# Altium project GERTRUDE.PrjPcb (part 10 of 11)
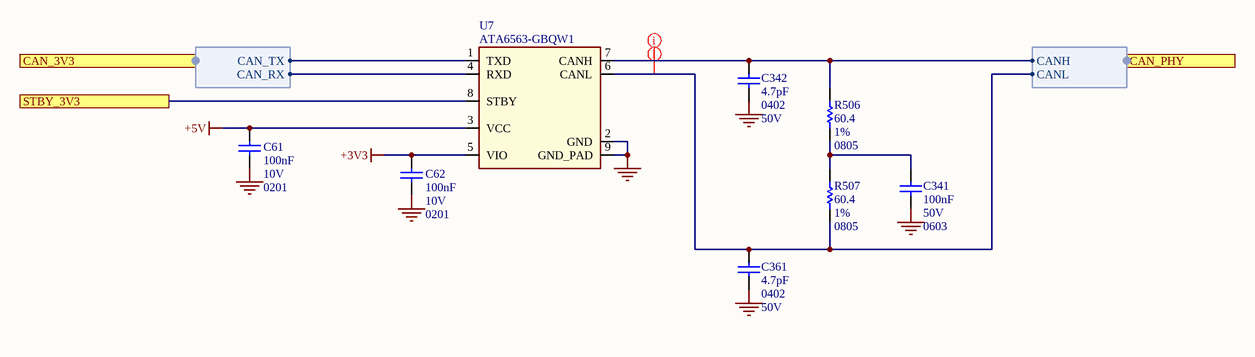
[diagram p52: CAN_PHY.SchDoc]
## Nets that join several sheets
7V-24V: USB_PD_CONTROLLER (D9.A), HEADERS_UNO (F2.1), POWER (11 pins), HEADERS_JOMEGA (8 pins), HEADERS_JMEDIA_JMISC (F3.1)
+1.28V: POWER_REGULATORS_CARRIER (5 pins), AUDIO_CODEC (C136.2 C146.2 U23.36)
+1V1: ETH_PHY (12 pins), POWER_REGULATORS_CARRIER (8 pins), PCIE_PACKET_SWITCH (11 pins), PCIE_USB (39 pins)
+1V8: U_ETH/U_ETH_PHY/U_LOAD_SWITCH_5V (U27_3.6 U27_3.11), POWER (R21.2 R22.2 R265.1 TP84.X), AUDIO_CODEC (7 pins), HDMI_CONVERTER (5 pins), STM32 (R218.1)
+3V3: TOP (11 pins), MODULE_PWR (27 pins), MODULE_CONTROL (12 pins), USB_MUX (R475.2), USB_PD_CONTROLLER (R275.1), U_USB/U_LOAD_SWITCH_5V (C179_1.2 U27_1.3), U_USB/U_LOAD_SWITCH_5V (C179_2.2 U27_2.3), U_ETH/U_ETH_PHY/U_LOAD_SWITCH_5V (C179_3.2 U27_3.3), ETH_RJ45 (J2.14 J2.16), POWER (9 pins), POWER_DCDC_SOM (23 pins), POWER_REGULATORS_CARRIER (9 pins), U_POWER/U_LOAD_SWITCH_5V (C179_4.2 U27_4.3), U_POWER/U_LOAD_SWITCH_5V (C179_5.2 U27_5.3 U27_5.6 U27_5.11), HDMI_CONVERTER (L16.1), U_MIPI/U_MIPI_MUX (C69_1.2 U10_1.1), U_MIPI/U_MIPI_MUX (C69_2.2 U10_2.1), U_MIPI/U_MIPI_FLAT_22PIN (D15_1.2 J3_1.22), U_MIPI/U_MIPI_FLAT_22PIN (D15_2.2 J3_2.22), U_MIPI/U_MIPI_MUX (C69_3.2 U10_3.1), U_MIPI/U_MIPI_FLAT_22PIN (D15_3.2 J3_3.22), U_MIPI/U_TRANSLATOR_4CH (C175_2.2 U21_2.11), HEADERS_JOMEGA (JOMEGA.91 JOMEGA.93 JOMEGA.95), STM32 (35 pins), U_MICROCONTROLLER/U_LED/U_LED_RGB (DL1_1.1), U_MICROCONTROLLER/U_LED/U_LED_RGB (DL1_2.1), U_MICROCONTROLLER/U_LED/U_LED_RGB (DL1_3.1), U_MICROCONTROLLER/U_LED/U_LED_RGB (DL1_4.1), ANALOG_SWITCH (C274.2 U28.4 U28.5), U_MICROCONTROLLER/U_TRANSLATOR_4CH (C175_3.2 U21_3.11), HEADERS_JMEDIA_JMISC (5 pins), HEADERS_JCTL (R317.2), T8CH_ (C174_5.2 U33_5.19), HEATSINK_FAN (C306.2 R261.2 R455.2 U32.5), PCIE (R327.1 R328.1 R329.1), PCIE_PACKET_SWITCH (37 pins), U_PCIE/U_PCIE_NVME/U_LOAD_SWITCH_5V (C179_6.2 U27_6.3 U27_6.6 U27_6.11), WIFI_BLE (12 pins), U_PCIE/U_WIFI_BLE/U_TRANSLATOR_4CH (C175_4.2 U21_4.11), PCIE_USB (13 pins), U_PCIE/U_TRANSLATOR_4CH (C175_5.2 U21_5.11), CAN_PHY (C62.2 U7.5)
+3V3_LIMITED: HEADERS_UNO (JANALOG.2 JANALOG.4), POWER (C222.2), U_POWER/U_LOAD_SWITCH_5V (U27_5.7 U27_5.8 U27_5.9 U27_5.10), HEADERS_JHAT (6 pins), U_HEADERS_JHAT/T8CH_ (C174_2.2 U33_2.19), U_HEADERS_JHAT/T8CH_ (C174_3.2 U33_3.19), U_HEADERS_JHAT/T8CH_ (C174_4.2 U33_4.19), U_HEADERS_JHAT/U_TRANSLATOR_4CH (C175_1.2 U21_1.11), QWIIC (C271.2 D82.2 J13.2)
+5V: USB_PD_CONTROLLER (R276.2), U_USB/U_LOAD_SWITCH_5V (U27_1.6 U27_1.11), U_USB/U_LOAD_SWITCH_5V (U27_2.6 U27_2.11), POWER (R336.1), POWER_REGULATORS_CARRIER (12 pins), U_POWER/U_LOAD_SWITCH_5V (U27_4.6 U27_4.11), AUDIO_CODEC (C165.2 C166.2 U23.14 U23.15), HDMI_CONNECTOR (D3.A R492.2 R495.2), HEADERS_JOMEGA (JOMEGA.97 JOMEGA.99), HEADERS_JMEDIA_JMISC (JMISC.54 JMISC.56), HEATSINK_FAN (5 pins), CAN_PHY (C61.2 U7.3)
+5V_LIMITED: HEADERS_UNO (JANALOG.5 JSPI.2), POWER (C221.2), U_POWER/U_LOAD_SWITCH_5V (U27_4.7 U27_4.8 U27_4.9 U27_4.10), HEADERS_JHAT (J6.2 J6.4)
CYPD_VDDIO: USB_MUX (R476.2), USB_PD_CONTROLLER (13 pins), U_USB/U_USB_PD_CONTROLLER/T8CH_ (C174_1.2 U33_1.19)
GND: TOP (12 pins), MODULE_GND (1526 pins), MODULE_PWR (12 pins), MODULE_SAIL (TP30.X), MODULE_SAIL_FLASH (7 pins), MODULE_STRAPS_MD (10 pins), MODULE_STRAPS_SAIL (13 pins), MODULE_CONTROL (12 pins), USB (12 pins), USB_USBC (19 pins), USB_MUX (13 pins), USB_PD_CONTROLLER (43 pins), U_USB/U_USB_PD_CONTROLLER/T8CH_ (5 pins), USB_USBA (16 pins), U_USB/U_LOAD_SWITCH_5V (C179_1.1 C246_1.1 U27_1.2), U_USB/U_LOAD_SWITCH_5V (C179_2.1 C246_2.1 U27_2.2), ETH (C67.1 C68.1 U8.3 U9.3), ETH_PHY (45 pins), U_ETH/U_ETH_PHY/U_LOAD_SWITCH_5V (C179_3.1 C246_3.1 U27_3.2), ETH_RJ45 (C66.2 R109.1), HEADERS_UNO (5 pins), POWER (30 pins), POWER_DCDC_SOM (51 pins), POWER_REGULATORS_CARRIER (49 pins), U_POWER/U_LOAD_SWITCH_5V (C179_4.1 C246_4.1 U27_4.2), U_POWER/U_LOAD_SWITCH_5V (C179_5.1 C246_5.1 U27_5.2), AUDIO_CODEC (24 pins), HEADERS_JHAT (8 pins), U_HEADERS_JHAT/T8CH_ (5 pins), U_HEADERS_JHAT/T8CH_ (5 pins), U_HEADERS_JHAT/T8CH_ (5 pins), U_HEADERS_JHAT/U_TRANSLATOR_4CH (C172_1.1 C175_1.1 C220_1.2 U21_1.6), VIDEO (5 pins), HDMI (R269.1), HDMI_CONNECTOR (18 pins), HDMI_CONVERTER (22 pins), U_MIPI/U_MIPI_MUX (8 pins), U_MIPI/U_MIPI_MUX (8 pins), U_MIPI/U_MIPI_FLAT_22PIN (17 pins), U_MIPI/U_MIPI_FLAT_22PIN (17 pins), U_MIPI/U_MIPI_MUX (8 pins), U_MIPI/U_MIPI_FLAT_22PIN (17 pins), U_MIPI/U_TRANSLATOR_4CH (C172_2.1 C175_2.1 C220_2.2 U21_2.6), PUSHBUTTONS (6 pins), HEADERS_JOMEGA (50 pins), MICROCONTROLLER (R184.1), STM32 (59 pins), QWIIC (6 pins), ANALOG_SWITCH (C274.1 U28.2), U_MICROCONTROLLER/U_TRANSLATOR_4CH (C172_3.1 C175_3.1 C220_3.2 U21_3.6), HEADERS_JMEDIA_JMISC (63 pins), HEADERS_JCTL (12 pins), T8CH_ (5 pins), HEATSINK_FAN (13 pins), PCIE (R315.1 R323.1 R468.1), PCIE_PACKET_SWITCH (42 pins), PCIE_NVME (40 pins), U_PCIE/U_PCIE_NVME/U_LOAD_SWITCH_5V (C179_6.1 C246_6.1 U27_6.2), WIFI_BLE (63 pins), U_PCIE/U_WIFI_BLE/U_TRANSLATOR_4CH (C172_4.1 C175_4.1 C220_4.2 U21_4.6), PCIE_USB (43 pins), U_PCIE/U_TRANSLATOR_4CH (C172_5.1 C175_5.1 C220_5.2 U21_5.6), CAN_PHY (7 pins)
SOM_VCOIN: MODULE_PWR (R399.1), HEADERS_JMEDIA_JMISC (R508.2)
SOM_VREG_MDPX3_1P8: TOP (10 pins), MODULE_PWR (MODULE1.BD42 MODULE1.BE42 MODULE1.BF42 TP88.X), MODULE_STRAPS_MD (10 pins), USB_PD_CONTROLLER (R330.1 R331.1 R332.1), U_USB/U_USB_PD_CONTROLLER/T8CH_ (C173_1.2 R168_1.2 U33_1.2), POWER (R21.1 R497.2), POWER_REGULATORS_CARRIER (R146.1 R147.1 U16.5 U17.5), AUDIO_CODEC (R270.2), HEADERS_JHAT (R422.1 R423.1 R424.1 R425.1), U_HEADERS_JHAT/T8CH_ (C173_2.2 R168_2.2 U33_2.2), U_HEADERS_JHAT/T8CH_ (C173_3.2 R168_3.2 U33_3.2), U_HEADERS_JHAT/T8CH_ (C173_4.2 R168_4.2 U33_4.2), U_HEADERS_JHAT/U_TRANSLATOR_4CH (C172_1.2 R326_1.2 U21_1.1), VIDEO (8 pins), U_MIPI/U_TRANSLATOR_4CH (C172_2.2 R326_2.2 U21_2.1), HEADERS_JOMEGA (JOMEGA.79 JOMEGA.81), MICROCONTROLLER (R412.1), STM32 (R351.1), U_MICROCONTROLLER/U_TRANSLATOR_4CH (C172_3.2 R326_3.2 U21_3.1), HEADERS_JMEDIA_JMISC (JMISC.57), HEADERS_JCTL (D63.2 JCTL.9 R166.1), T8CH_ (C173_5.2 R168_5.2 U33_5.2), PCIE (R319.1 R320.1 R321.1 R322.2), PCIE_NVME (R224.1 R414.2 R415.2 R416.2), WIFI_BLE (R23.2 R314.1 R465.2), U_PCIE/U_WIFI_BLE/U_TRANSLATOR_4CH (C172_4.2 R326_4.2 U21_4.1), U_PCIE/U_TRANSLATOR_4CH (C172_5.2 R326_5.2 U21_5.1)
SOM_VREG_S5S_SPX3_1P8: MODULE_PWR (MODULE1.AW45 MODULE1.AW46), MODULE_SAIL (TP1.X), MODULE_SAIL_FLASH (12 pins), MODULE_STRAPS_SAIL (13 pins), HEADERS_JOMEGA (JOMEGA.77), HEADERS_JCTL (R458.1)
VBAT: STM32 (C63.2 C282.2 U3.D3), HEADERS_JMEDIA_JMISC (R509.2)
1V05_PG (PULLUP 1V8): ETH_PHY (R85.1), POWER (R265.2), POWER_REGULATORS_CARRIER (U17.1)
3V3_PG (PULLUP 3V3): TOP (R349.1), POWER_DCDC_SOM (R124.2 U11.1 U11.2)
A_CLK_N: U_MIPI/U_MIPI_MUX (U10_1.18), HEADERS_JMEDIA_JMISC (D91.1 D91.10 JMEDIA.3)
A_CLK_N: U_MIPI/U_MIPI_MUX (U10_2.18), HEADERS_JMEDIA_JMISC (D93.4 D93.7 JMEDIA.33)
A_CLK_N: U_MIPI/U_MIPI_MUX (U10_3.18), HEADERS_JMEDIA_JMISC (D96.2 D96.9 JMEDIA.42)
A_CLK_P: U_MIPI/U_MIPI_MUX (U10_1.19), HEADERS_JMEDIA_JMISC (D91.2 D91.9 JMEDIA.5)
A_CLK_P: U_MIPI/U_MIPI_MUX (U10_2.19), HEADERS_JMEDIA_JMISC (D93.5 D93.6 JMEDIA.35)
A_CLK_P: U_MIPI/U_MIPI_MUX (U10_3.19), HEADERS_JMEDIA_JMISC (D96.1 D96.10 JMEDIA.40)
A_LN0_N: U_MIPI/U_MIPI_MUX (U10_1.37), HEADERS_JMEDIA_JMISC (D90.1 D90.10 JMEDIA.12)
A_LN0_N: U_MIPI/U_MIPI_MUX (U10_2.37), HEADERS_JMEDIA_JMISC (D92.4 D92.7 JMEDIA.21)
A_LN0_N: U_MIPI/U_MIPI_MUX (U10_3.37), HEADERS_JMEDIA_JMISC (D97.2 D97.9 JMEDIA.54)
A_LN0_P: U_MIPI/U_MIPI_MUX (U10_1.38), HEADERS_JMEDIA_JMISC (D90.2 D90.9 JMEDIA.10)
A_LN0_P: U_MIPI/U_MIPI_MUX (U10_2.38), HEADERS_JMEDIA_JMISC (D92.5 D92.6 JMEDIA.23)
A_LN0_P: U_MIPI/U_MIPI_MUX (U10_3.38), HEADERS_JMEDIA_JMISC (D97.1 D97.10 JMEDIA.52)
A_LN1_N: U_MIPI/U_MIPI_MUX (U10_1.35), HEADERS_JMEDIA_JMISC (D90.4 D90.7 JMEDIA.6)
A_LN1_N: U_MIPI/U_MIPI_MUX (U10_2.35), HEADERS_JMEDIA_JMISC (D93.1 D93.10 JMEDIA.27)
A_LN1_N: U_MIPI/U_MIPI_MUX (U10_3.35), HEADERS_JMEDIA_JMISC (D96.5 D96.6 JMEDIA.48)
A_LN1_P: U_MIPI/U_MIPI_MUX (U10_1.36), HEADERS_JMEDIA_JMISC (D90.5 D90.6 JMEDIA.4)
A_LN1_P: U_MIPI/U_MIPI_MUX (U10_2.36), HEADERS_JMEDIA_JMISC (D93.2 D93.9 JMEDIA.29)
A_LN1_P: U_MIPI/U_MIPI_MUX (U10_3.36), HEADERS_JMEDIA_JMISC (D96.4 D96.7 JMEDIA.46)
A_LN2_N: U_MIPI/U_MIPI_MUX (U10_1.33), HEADERS_JMEDIA_JMISC (D91.4 D91.7 JMEDIA.9)
A_LN2_N: U_MIPI/U_MIPI_MUX (U10_2.33), HEADERS_JMEDIA_JMISC (D94.1 D94.10 JMEDIA.39)
A_LN2_N: U_MIPI/U_MIPI_MUX (U10_3.33), HEADERS_JMEDIA_JMISC (D95.5 D95.6 JMEDIA.36)
A_LN2_P: U_MIPI/U_MIPI_MUX (U10_1.34), HEADERS_JMEDIA_JMISC (D91.5 D91.6 JMEDIA.11)
A_LN2_P: U_MIPI/U_MIPI_MUX (U10_2.34), HEADERS_JMEDIA_JMISC (D94.2 D94.9 JMEDIA.41)
A_LN2_P: U_MIPI/U_MIPI_MUX (U10_3.34), HEADERS_JMEDIA_JMISC (D95.4 D95.7 JMEDIA.34)
A_LN3_N: U_MIPI/U_MIPI_MUX (U10_1.31), HEADERS_JMEDIA_JMISC (D92.1 D92.10 JMEDIA.15)
A_LN3_N: U_MIPI/U_MIPI_MUX (U10_2.31), HEADERS_JMEDIA_JMISC (D94.4 D94.7 JMEDIA.45)
A_LN3_N: U_MIPI/U_MIPI_MUX (U10_3.31), HEADERS_JMEDIA_JMISC (D95.2 D95.9 JMEDIA.30)
A_LN3_P: U_MIPI/U_MIPI_MUX (U10_1.32), HEADERS_JMEDIA_JMISC (D92.2 D92.9 JMEDIA.17)
A_LN3_P: U_MIPI/U_MIPI_MUX (U10_2.32), HEADERS_JMEDIA_JMISC (D94.5 D94.6 JMEDIA.47)
A_LN3_P: U_MIPI/U_MIPI_MUX (U10_3.32), HEADERS_JMEDIA_JMISC (D95.1 D95.10 JMEDIA.28)
B_CLK_N: HDMI_CONVERTER (U22.F2), U_MIPI/U_MIPI_MUX (U10_1.20)
B_CLK_N: U_MIPI/U_MIPI_MUX (U10_2.20), U_MIPI/U_MIPI_FLAT_22PIN (D7_2.1 D7_2.10 J3_2.8)
B_CLK_N: U_MIPI/U_MIPI_FLAT_22PIN (D7_1.1 D7_1.10 J3_1.8), U_MIPI/U_MIPI_MUX (U10_3.20)
B_CLK_P: HDMI_CONVERTER (U22.G2), U_MIPI/U_MIPI_MUX (U10_1.21)
B_CLK_P: U_MIPI/U_MIPI_MUX (U10_2.21), U_MIPI/U_MIPI_FLAT_22PIN (D7_2.2 D7_2.9 J3_2.9)
B_CLK_P: U_MIPI/U_MIPI_FLAT_22PIN (D7_1.2 D7_1.9 J3_1.9), U_MIPI/U_MIPI_MUX (U10_3.21)
B_LN0_N: HDMI_CONVERTER (U22.F3), U_MIPI/U_MIPI_MUX (U10_1.28)
B_LN0_N: U_MIPI/U_MIPI_MUX (U10_2.28), U_MIPI/U_MIPI_FLAT_22PIN (D6_2.1 D6_2.10 J3_2.2)
B_LN0_N: U_MIPI/U_MIPI_FLAT_22PIN (D6_1.1 D6_1.10 J3_1.2), U_MIPI/U_MIPI_MUX (U10_3.28)
B_LN0_P: HDMI_CONVERTER (U22.G3), U_MIPI/U_MIPI_MUX (U10_1.29)
B_LN0_P: U_MIPI/U_MIPI_MUX (U10_2.29), U_MIPI/U_MIPI_FLAT_22PIN (D6_2.2 D6_2.9 J3_2.3)
B_LN0_P: U_MIPI/U_MIPI_FLAT_22PIN (D6_1.2 D6_1.9 J3_1.3), U_MIPI/U_MIPI_MUX (U10_3.29)
B_LN1_N: HDMI_CONVERTER (U22.F4), U_MIPI/U_MIPI_MUX (U10_1.26)
B_LN1_N: U_MIPI/U_MIPI_MUX (U10_2.26), U_MIPI/U_MIPI_FLAT_22PIN (D6_2.4 D6_2.7 J3_2.5)
B_LN1_N: U_MIPI/U_MIPI_FLAT_22PIN (D6_1.4 D6_1.7 J3_1.5), U_MIPI/U_MIPI_MUX (U10_3.26)
B_LN1_P: HDMI_CONVERTER (U22.G4), U_MIPI/U_MIPI_MUX (U10_1.27)
B_LN1_P: U_MIPI/U_MIPI_MUX (U10_2.27), U_MIPI/U_MIPI_FLAT_22PIN (D6_2.5 D6_2.6 J3_2.6)
B_LN1_P: U_MIPI/U_MIPI_FLAT_22PIN (D6_1.5 D6_1.6 J3_1.6), U_MIPI/U_MIPI_MUX (U10_3.27)
B_LN2_N: HDMI_CONVERTER (U22.F5), U_MIPI/U_MIPI_MUX (U10_1.24)
B_LN2_N: U_MIPI/U_MIPI_MUX (U10_2.24), U_MIPI/U_MIPI_FLAT_22PIN (D7_2.4 D7_2.7 J3_2.11)
B_LN2_N: U_MIPI/U_MIPI_FLAT_22PIN (D7_1.4 D7_1.7 J3_1.11), U_MIPI/U_MIPI_MUX (U10_3.24)
B_LN2_P: HDMI_CONVERTER (U22.G5), U_MIPI/U_MIPI_MUX (U10_1.25)
B_LN2_P: U_MIPI/U_MIPI_MUX (U10_2.25), U_MIPI/U_MIPI_FLAT_22PIN (D7_2.5 D7_2.6 J3_2.12)
B_LN2_P: U_MIPI/U_MIPI_FLAT_22PIN (D7_1.5 D7_1.6 J3_1.12), U_MIPI/U_MIPI_MUX (U10_3.25)
B_LN3_N: HDMI_CONVERTER (U22.F6), U_MIPI/U_MIPI_MUX (U10_1.22)
B_LN3_N: U_MIPI/U_MIPI_MUX (U10_2.22), U_MIPI/U_MIPI_FLAT_22PIN (D8_2.1 D8_2.10 J3_2.14)
B_LN3_N: U_MIPI/U_MIPI_FLAT_22PIN (D8_1.1 D8_1.10 J3_1.14), U_MIPI/U_MIPI_MUX (U10_3.22)
B_LN3_P: HDMI_CONVERTER (U22.G6), U_MIPI/U_MIPI_MUX (U10_1.23)
B_LN3_P: U_MIPI/U_MIPI_MUX (U10_2.23), U_MIPI/U_MIPI_FLAT_22PIN (D8_2.2 D8_2.9 J3_2.15)
B_LN3_P: U_MIPI/U_MIPI_FLAT_22PIN (D8_1.2 D8_1.9 J3_1.15), U_MIPI/U_MIPI_MUX (U10_3.23)
BOOT0: HEADERS_UNO (JANALOG.1), MICROCONTROLLER (R151.1), STM32 (R352.2 R385.1 TP90.X)
CLKREQ_N_1V8: MODULE_MD (MODULE1.AW17), PCIE (R320.2), U_PCIE/U_TRANSLATOR_4CH (U21_5.3)
CLKREQ_N_3V3: PCIE (R328.2), PCIE_PACKET_SWITCH (U34.AM34), U_PCIE/U_TRANSLATOR_4CH (U21_5.9)
CSI0_CK_N: MODULE_MD (MODULE1.AK45), U_MIPI/U_MIPI_MUX (U10_2.15)
CSI0_CK_P: MODULE_MD (MODULE1.AK46), U_MIPI/U_MIPI_MUX (U10_2.14)
CSI0_L0_N: MODULE_MD (MODULE1.AL44), U_MIPI/U_MIPI_MUX (U10_2.6)
CSI0_L0_P: MODULE_MD (MODULE1.AL45), U_MIPI/U_MIPI_MUX (U10_2.5)
CSI0_L1_N: MODULE_MD (MODULE1.AM45), U_MIPI/U_MIPI_MUX (U10_2.8)
CSI0_L1_P: MODULE_MD (MODULE1.AM46), U_MIPI/U_MIPI_MUX (U10_2.7)
CSI0_L2_N: MODULE_MD (MODULE1.AN44), U_MIPI/U_MIPI_MUX (U10_2.11)
CSI0_L2_P: MODULE_MD (MODULE1.AN45), U_MIPI/U_MIPI_MUX (U10_2.10)
CSI0_L3_N: MODULE_MD (MODULE1.AP45), U_MIPI/U_MIPI_MUX (U10_2.13)
CSI0_L3_P: MODULE_MD (MODULE1.AP46), U_MIPI/U_MIPI_MUX (U10_2.12)
CSI1_CK_N: MODULE_MD (MODULE1.AE44), U_MIPI/U_MIPI_MUX (U10_3.15)
CSI1_CK_P: MODULE_MD (MODULE1.AE45), U_MIPI/U_MIPI_MUX (U10_3.14)
CSI1_L0_N: MODULE_MD (MODULE1.AF45), U_MIPI/U_MIPI_MUX (U10_3.6)
CSI1_L0_P: MODULE_MD (MODULE1.AF46), U_MIPI/U_MIPI_MUX (U10_3.5)
CSI1_L1_N: MODULE_MD (MODULE1.AG44), U_MIPI/U_MIPI_MUX (U10_3.8)
CSI1_L1_P: MODULE_MD (MODULE1.AG45), U_MIPI/U_MIPI_MUX (U10_3.7)
CSI1_L2_N: MODULE_MD (MODULE1.AH45), U_MIPI/U_MIPI_MUX (U10_3.11)
CSI1_L2_P: MODULE_MD (MODULE1.AH46), U_MIPI/U_MIPI_MUX (U10_3.10)
CSI1_L3_N: MODULE_MD (MODULE1.AJ44), U_MIPI/U_MIPI_MUX (U10_3.13)
CSI1_L3_P: MODULE_MD (MODULE1.AJ45), U_MIPI/U_MIPI_MUX (U10_3.12)
CSI2_CK_N: MODULE_MD (MODULE1.Y45), U_MIPI/U_MIPI_FLAT_22PIN (D7_3.1 D7_3.10 J3_3.8)
CSI2_CK_P: MODULE_MD (MODULE1.Y46), U_MIPI/U_MIPI_FLAT_22PIN (D7_3.2 D7_3.9 J3_3.9)
CSI2_L0_N: MODULE_MD (MODULE1.AA44), U_MIPI/U_MIPI_FLAT_22PIN (D6_3.1 D6_3.10 J3_3.2)
CSI2_L0_P: MODULE_MD (MODULE1.AA45), U_MIPI/U_MIPI_FLAT_22PIN (D6_3.2 D6_3.9 J3_3.3)
CSI2_L1_N: MODULE_MD (MODULE1.AB45), U_MIPI/U_MIPI_FLAT_22PIN (D6_3.4 D6_3.7 J3_3.5)
CSI2_L1_P: MODULE_MD (MODULE1.AB46), U_MIPI/U_MIPI_FLAT_22PIN (D6_3.5 D6_3.6 J3_3.6)
CSI2_L2_N: MODULE_MD (MODULE1.AC44), U_MIPI/U_MIPI_FLAT_22PIN (D7_3.4 D7_3.7 J3_3.11)
CSI2_L2_P: MODULE_MD (MODULE1.AC45), U_MIPI/U_MIPI_FLAT_22PIN (D7_3.5 D7_3.6 J3_3.12)
CSI2_L3_N: MODULE_MD (MODULE1.AD45), U_MIPI/U_MIPI_FLAT_22PIN (D8_3.1 D8_3.10 J3_3.14)
CSI2_L3_P: MODULE_MD (MODULE1.AD46), U_MIPI/U_MIPI_FLAT_22PIN (D8_3.2 D8_3.9 J3_3.15)
CTS_1V8: MODULE_MD (MODULE1.AA41), U_HEADERS_JHAT/U_TRANSLATOR_4CH (U21_1.5), WIFI_BLE (R380.1)
DSI0_CK_N: MODULE_MD (MODULE1.T46), U_MIPI/U_MIPI_MUX (U10_1.15)
DSI0_CK_P: MODULE_MD (MODULE1.T45), U_MIPI/U_MIPI_MUX (U10_1.14)
DSI0_L0_N: MODULE_MD (MODULE1.P46), U_MIPI/U_MIPI_MUX (U10_1.6)
DSI0_L0_P: MODULE_MD (MODULE1.P45), U_MIPI/U_MIPI_MUX (U10_1.5)
DSI0_L1_N: MODULE_MD (MODULE1.R45), U_MIPI/U_MIPI_MUX (U10_1.8)
DSI0_L1_P: MODULE_MD (MODULE1.R44), U_MIPI/U_MIPI_MUX (U10_1.7)
DSI0_L2_N: MODULE_MD (MODULE1.U45), U_MIPI/U_MIPI_MUX (U10_1.11)
DSI0_L2_P: MODULE_MD (MODULE1.U44), U_MIPI/U_MIPI_MUX (U10_1.10)
DSI0_L3_N: MODULE_MD (MODULE1.V46), U_MIPI/U_MIPI_MUX (U10_1.13)
DSI0_L3_P: MODULE_MD (MODULE1.V45), U_MIPI/U_MIPI_MUX (U10_1.12)
DVDD18: ETH (C67.2 C68.2 U8.5 U9.5), ETH_PHY (19 pins), U_ETH/U_ETH_PHY/U_LOAD_SWITCH_5V (U27_3.7 U27_3.8 U27_3.9 U27_3.10)
EDP0_AUX_N: MODULE_MD (MODULE1.B29), USB_PD_CONTROLLER (U5.35)
EDP0_AUX_P: MODULE_MD (MODULE1.A29), USB_PD_CONTROLLER (U5.36)
EDP0_TX0_N: MODULE_MD (MODULE1.B21), USB_MUX (U6.40)
EDP0_TX0_P: MODULE_MD (MODULE1.A21), USB_MUX (U6.39)
EDP0_TX1_N: MODULE_MD (MODULE1.B23), USB_MUX (U6.3)
EDP0_TX1_P: MODULE_MD (MODULE1.A23), USB_MUX (U6.2)
EDP0_TX2_N: MODULE_MD (MODULE1.B25), USB_MUX (U6.6)
EDP0_TX2_P: MODULE_MD (MODULE1.A25), USB_MUX (U6.5)
EDP0_TX3_N: MODULE_MD (MODULE1.B27), USB_MUX (U6.9)
EDP0_TX3_P: MODULE_MD (MODULE1.A27), USB_MUX (U6.8)
ETH_PHY_TRX0_N: ETH_PHY (R70.2 U1.54), ETH_RJ45 (J2.10)
ETH_PHY_TRX0_P: ETH_PHY (R69.2 U1.53), ETH_RJ45 (J2.11)
ETH_PHY_TRX1_N: ETH_PHY (R72.2 U1.5), ETH_RJ45 (J2.5)
ETH_PHY_TRX1_P: ETH_PHY (R71.2 U1.4), ETH_RJ45 (J2.4)
ETH_PHY_TRX2_N: ETH_PHY (R74.2 U1.10), ETH_RJ45 (J2.2)
ETH_PHY_TRX2_P: ETH_PHY (R73.2 U1.9), ETH_RJ45 (J2.3)
ETH_PHY_TRX3_N: ETH_PHY (R76.2 U1.17), ETH_RJ45 (J2.9)
ETH_PHY_TRX3_P: ETH_PHY (R75.2 U1.16), ETH_RJ45 (J2.8)
FLAT0_GPIO_PIN17_3V3: VIDEO (R389.1), U_MIPI/U_MIPI_FLAT_22PIN (D8_2.4 D8_2.7 J3_2.17), U_MIPI/U_TRANSLATOR_4CH (U21_2.10)
FLAT1_GPIO_PIN17_3V3: VIDEO (R390.1), U_MIPI/U_MIPI_FLAT_22PIN (D8_1.4 D8_1.7 J3_1.17), U_MIPI/U_TRANSLATOR_4CH (U21_2.9)
FLAT2_GPIO_PIN17_3V3: VIDEO (R391.1), U_MIPI/U_MIPI_FLAT_22PIN (D8_3.4 D8_3.7 J3_3.17), U_MIPI/U_TRANSLATOR_4CH (U21_2.8)
FORCE_BOOT_3V3: TOP (R484.1), HEADERS_JOMEGA (JOMEGA.89), HEADERS_JCTL (6 pins)
GPIO4_SWDIO: USB_PD_CONTROLLER (TP39.X U5.27), U_USB/U_USB_PD_CONTROLLER/T8CH_ (U33_1.16)
GPIO5_SWCLK: USB_PD_CONTROLLER (TP38.X U5.28), U_USB/U_USB_PD_CONTROLLER/T8CH_ (U33_1.15)
GPIO_0: MODULE_MD (MODULE1.AY17), PCIE (R319.2), U_PCIE/U_TRANSLATOR_4CH (U21_5.2)
GPIO_2: MODULE_MD (MODULE1.AY16), PCIE (R321.2), U_PCIE/U_TRANSLATOR_4CH (U21_5.4)
GPIO_4: MODULE_MD (MODULE1.AW25), ETH_PHY (R284.1 R285.1 R413.1)
GPIO_5: MODULE_MD (MODULE1.AY24), ETH_PHY (R266.1 U1.33)
GPIO_6: MODULE_MD (MODULE1.AW24), ETH_PHY (R267.1 U1.34)
GPIO_7: MODULE_MD (MODULE1.BA11), MODULE_STRAPS_MD (R13.2 R28.2)
GPIO_8: MODULE_MD (MODULE1.AY11), MODULE_STRAPS_MD (R15.2 R30.2)
GPIO_21: MODULE_MD (MODULE1.AW19), PCIE_NVME (R414.1 R417.2)
GPIO_22: MODULE_MD (MODULE1.AY20), PCIE_NVME (R415.1 R418.2)
GPIO_23: MODULE_MD (MODULE1.AW20), PCIE_NVME (R416.1 R419.2)
GPIO_50: MODULE_MD (MODULE1.AB43), ETH_PHY (U1.35)
GPIO_53: MODULE_MD (MODULE1.AW11), MODULE_STRAPS_MD (R12.2 R27.2)
GPIO_66: MODULE_MD (MODULE1.Y42), MODULE_STRAPS_MD (R14.2 R29.2)
GPIO_76: MODULE_MD (MODULE1.V38), MODULE_STRAPS_MD (R2.2 R17.2)
GPIO_91: MODULE_MD (MODULE1.AE42), MODULE_STRAPS_MD (R1.2 R16.2)
GPIO_97: MODULE_MD (MODULE1.E26), MODULE_STRAPS_MD (R3.2 R18.2)
GPIO_98: MODULE_MD (MODULE1.E23), MODULE_STRAPS_MD (R4.2 R19.2)
GPIO_102: MODULE_MD (MODULE1.D26), MODULE_STRAPS_MD (R5.2 R20.2)
HDMI_CLK_N: HDMI_CONNECTOR (D14.5 D14.6 J4.12), HDMI_CONVERTER (U22.B7)
HDMI_CLK_P: HDMI_CONNECTOR (D14.4 D14.7 J4.10), HDMI_CONVERTER (U22.A7)
HDMI_TX0_N: HDMI_CONNECTOR (D13.5 D13.6 J4.9), HDMI_CONVERTER (U22.A6)
HDMI_TX0_P: HDMI_CONNECTOR (D13.4 D13.7 J4.7), HDMI_CONVERTER (U22.A5)
HDMI_TX1_N: HDMI_CONNECTOR (D14.2 D14.9 J4.6), HDMI_CONVERTER (U22.A4)
HDMI_TX1_P: HDMI_CONNECTOR (D14.1 D14.10 J4.4), HDMI_CONVERTER (U22.A3)
HDMI_TX2_N: HDMI_CONNECTOR (D13.2 D13.9 J4.3), HDMI_CONVERTER (U22.A2)
HDMI_TX2_P: HDMI_CONNECTOR (D13.1 D13.10 J4.1), HDMI_CONVERTER (U22.A1)
I2C1_IRQ: USB_PD_CONTROLLER (R99.1 R333.2), U_USB/U_USB_PD_CONTROLLER/T8CH_ (U33_1.20)
I2C1_SCL: USB_PD_CONTROLLER (R100.1 R334.2), U_USB/U_USB_PD_CONTROLLER/T8CH_ (U33_1.18)
I2C1_SDA: USB_PD_CONTROLLER (R101.1 R335.2), U_USB/U_USB_PD_CONTROLLER/T8CH_ (U33_1.17)
I2S_DATA0: MODULE_MD (MODULE1.A32), U_HEADERS_JHAT/U_TRANSLATOR_4CH (U21_1.3)
I2S_DATA1: MODULE_MD (MODULE1.A34), U_HEADERS_JHAT/U_TRANSLATOR_4CH (U21_1.2)
I2S_SCK: MODULE_MD (MODULE1.A31), U_HEADERS_JHAT/T8CH_ (U33_2.3)
I2S_WS: MODULE_MD (MODULE1.A33), U_HEADERS_JHAT/T8CH_ (U33_4.1)
JHAT_GPIO_0: HEADERS_JHAT (J6.27 R171.2), U_HEADERS_JHAT/T8CH_ (U33_4.13)
JHAT_GPIO_1: HEADERS_JHAT (J6.28 R122.2), U_HEADERS_JHAT/T8CH_ (U33_4.14)
JHAT_GPIO_2: HEADERS_JHAT (J6.3 R170.2), U_HEADERS_JHAT/T8CH_ (U33_2.12)
JHAT_GPIO_3: HEADERS_JHAT (J6.5 R169.2), U_HEADERS_JHAT/T8CH_ (U33_2.13)
JHAT_GPIO_4: HEADERS_JHAT (J6.7), U_HEADERS_JHAT/T8CH_ (U33_2.15)
JHAT_GPIO_5: HEADERS_JHAT (J6.29), U_HEADERS_JHAT/T8CH_ (U33_4.15)
JHAT_GPIO_6: HEADERS_JHAT (J6.31), U_HEADERS_JHAT/T8CH_ (U33_4.16)
JHAT_GPIO_7: HEADERS_JHAT (J6.26), U_HEADERS_JHAT/T8CH_ (U33_4.12)
JHAT_GPIO_8: HEADERS_JHAT (J6.24), U_HEADERS_JHAT/T8CH_ (U33_3.20)
JHAT_GPIO_9: HEADERS_JHAT (J6.21), U_HEADERS_JHAT/T8CH_ (U33_3.16)
JHAT_GPIO_10: HEADERS_JHAT (J6.19), U_HEADERS_JHAT/T8CH_ (U33_3.14)
JHAT_GPIO_11: HEADERS_JHAT (J6.23), U_HEADERS_JHAT/T8CH_ (U33_3.17)
JHAT_GPIO_12: HEADERS_JHAT (J6.32), U_HEADERS_JHAT/T8CH_ (U33_4.17)
JHAT_GPIO_13: HEADERS_JHAT (J6.33), U_HEADERS_JHAT/T8CH_ (U33_4.18)
JHAT_GPIO_14: HEADERS_JHAT (J6.8), U_HEADERS_JHAT/T8CH_ (U33_2.14)
JHAT_GPIO_15: HEADERS_JHAT (J6.10), U_HEADERS_JHAT/T8CH_ (U33_2.16)
JHAT_GPIO_16: HEADERS_JHAT (J6.36), U_HEADERS_JHAT/U_TRANSLATOR_4CH (U21_1.7)
JHAT_GPIO_17: HEADERS_JHAT (J6.11), U_HEADERS_JHAT/T8CH_ (U33_2.17)
JHAT_GPIO_18: HEADERS_JHAT (J6.12), U_HEADERS_JHAT/T8CH_ (U33_2.18)
JHAT_GPIO_19: HEADERS_JHAT (J6.35), U_HEADERS_JHAT/T8CH_ (U33_4.20)
JHAT_GPIO_20: HEADERS_JHAT (J6.38), U_HEADERS_JHAT/U_TRANSLATOR_4CH (U21_1.9)
JHAT_GPIO_21: HEADERS_JHAT (J6.40), U_HEADERS_JHAT/U_TRANSLATOR_4CH (U21_1.10)
JHAT_GPIO_22: HEADERS_JHAT (J6.15), U_HEADERS_JHAT/T8CH_ (U33_3.12)
JHAT_GPIO_23: HEADERS_JHAT (J6.16), U_HEADERS_JHAT/T8CH_ (U33_3.13)
JHAT_GPIO_24: HEADERS_JHAT (J6.18), U_HEADERS_JHAT/T8CH_ (U33_3.15)
JHAT_GPIO_25: HEADERS_JHAT (J6.22), U_HEADERS_JHAT/T8CH_ (U33_3.18)
JHAT_GPIO_26: HEADERS_JHAT (J6.37), U_HEADERS_JHAT/U_TRANSLATOR_4CH (U21_1.8)
JHAT_GPIO_27: HEADERS_JHAT (J6.13), U_HEADERS_JHAT/T8CH_ (U33_2.20)
MD_CCI_I2C0.SCL: TOP (R252.2), MODULE_MD (MODULE1.AJ41), HEADERS_JMEDIA_JMISC (D83.2 JMEDIA.51), T8CH_ (U33_5.4)
MD_CCI_I2C0.SDA: TOP (R253.2), MODULE_MD (MODULE1.AJ40), HEADERS_JMEDIA_JMISC (D84.2 JMEDIA.53), T8CH_ (U33_5.5)
MD_CCI_I2C0_3V3.SCL: TOP (R159.2), U_MIPI/U_MIPI_FLAT_22PIN (D10_2.2 J3_2.20), T8CH_ (U33_5.17)
MD_CCI_I2C0_3V3.SDA: TOP (R160.2), U_MIPI/U_MIPI_FLAT_22PIN (D11_2.2 J3_2.21), T8CH_ (U33_5.16)
MD_CCI_I2C2.SCL: TOP (R254.2), MODULE_MD (MODULE1.AK42), HEADERS_JMEDIA_JMISC (D89.2 JMEDIA.24), T8CH_ (U33_5.6)
MD_CCI_I2C2.SDA: TOP (R255.2), MODULE_MD (MODULE1.AJ39), HEADERS_JMEDIA_JMISC (D88.2 JMEDIA.22), T8CH_ (U33_5.7)
MD_CCI_I2C2_3V3.SCL: TOP (R164.2), U_MIPI/U_MIPI_FLAT_22PIN (D10_1.2 J3_1.20), T8CH_ (U33_5.15)
MD_CCI_I2C2_3V3.SDA: TOP (R175.2), U_MIPI/U_MIPI_FLAT_22PIN (D11_1.2 J3_1.21), T8CH_ (U33_5.14)
MD_CCI_I2C3.SCL: MODULE_MD (MODULE1.AD40), STM32 (U3.C6)
MD_CCI_I2C3.SDA: MODULE_MD (MODULE1.AY25), STM32 (U3.A5)
MD_CCI_I2C4.SCL: TOP (R256.2), MODULE_MD (MODULE1.AG42), T8CH_ (U33_5.8)
MD_CCI_I2C4.SDA: TOP (R257.2), MODULE_MD (MODULE1.AG41), T8CH_ (U33_5.9)
MD_CCI_I2C4_3V3.SCL: TOP (R176.2), U_MIPI/U_MIPI_FLAT_22PIN (D10_3.2 J3_3.20), T8CH_ (U33_5.13)
MD_CCI_I2C4_3V3.SDA: TOP (R177.2), U_MIPI/U_MIPI_FLAT_22PIN (D11_3.2 J3_3.21), T8CH_ (U33_5.12)
MD_GPIO_3: MODULE_MD (MODULE1.D37), USB_PD_CONTROLLER (R186.1 R330.2)
MD_GPIO_10: MODULE_MD (MODULE1.AW30), HEADERS_JMEDIA_JMISC (D101.1 D101.10 JMISC.37)
MD_GPIO_11: MODULE_MD (MODULE1.AV29), HEADERS_JMEDIA_JMISC (D101.2 D101.9 JMISC.39)
MD_GPIO_12: MODULE_MD (MODULE1.AY30), HEADERS_JMEDIA_JMISC (D101.4 D101.7 JMISC.41)
MD_GPIO_13: MODULE_MD (MODULE1.AW29), HEADERS_JMEDIA_JMISC (D101.5 D101.6 JMISC.43)
MD_GPIO_14: MODULE_MD (MODULE1.AY28), HEADERS_JMEDIA_JMISC (D102.2 D102.9 JMISC.47)
MD_GPIO_15: MODULE_MD (MODULE1.AW28), HEADERS_JMEDIA_JMISC (D102.1 D102.10 JMISC.45)
MD_GPIO_16: MODULE_MD (MODULE1.AV28), AUDIO_CODEC (R270.1 U23.43)
MD_GPIO_17: MODULE_MD (MODULE1.E34), HEADERS_JHAT (R423.2), U_HEADERS_JHAT/T8CH_ (U33_2.9)
MD_GPIO_18: MODULE_MD (MODULE1.E33), HEADERS_JHAT (R422.2), U_HEADERS_JHAT/T8CH_ (U33_2.8)
MD_GPIO_19: MODULE_MD (MODULE1.C37), HEADERS_JHAT (R425.2), U_HEADERS_JHAT/T8CH_ (U33_4.8)
MD_GPIO_20: MODULE_MD (MODULE1.B37), HEADERS_JHAT (R424.2), U_HEADERS_JHAT/T8CH_ (U33_4.7)
MD_GPIO_24: MODULE_MD (MODULE1.E37), VIDEO (R165.1), U_MIPI/U_MIPI_MUX (U10_2.17)
MD_GPIO_25: MODULE_MD (MODULE1.Y40), U_HEADERS_JHAT/T8CH_ (U33_3.5)
MD_GPIO_26: MODULE_MD (MODULE1.Y43), U_HEADERS_JHAT/T8CH_ (U33_3.7)
MD_GPIO_27: MODULE_MD (MODULE1.V40), U_HEADERS_JHAT/T8CH_ (U33_3.4)
MD_GPIO_28: MODULE_MD (MODULE1.V39), U_HEADERS_JHAT/T8CH_ (U33_3.1)
MD_GPIO_29: MODULE_MD (MODULE1.AD41), PCIE_NVME (R226.1)
MD_GPIO_30: MODULE_MD (MODULE1.AD42), PCIE_NVME (R225.1)
MD_GPIO_37: MODULE_MD (MODULE1.Y39), HEADERS_JOMEGA (D36.4 D36.7 JOMEGA.66)
MD_GPIO_38: MODULE_MD (MODULE1.W40), HEADERS_JOMEGA (D36.5 D36.6 JOMEGA.68)
MD_GPIO_39: MODULE_MD (MODULE1.W41), HEADERS_JOMEGA (D36.1 D36.10 JOMEGA.62)
MD_GPIO_40: MODULE_MD (MODULE1.W42), HEADERS_JOMEGA (D36.2 D36.9 JOMEGA.64)
MD_GPIO_41: MODULE_MD (MODULE1.AC40), VIDEO (R387.1), U_MIPI/U_MIPI_MUX (U10_3.17)
MD_GPIO_42: MODULE_MD (MODULE1.AC39), MICROCONTROLLER (R408.2)
MD_GPIO_43: MODULE_MD (MODULE1.Y41), HEADERS_JOMEGA (JOMEGA.83), HEADERS_JCTL (D65.2 JCTL.4)
MD_GPIO_44: MODULE_MD (MODULE1.D36), HEADERS_JOMEGA (JOMEGA.85), HEADERS_JCTL (D66.2 JCTL.6)
MD_GPIO_45: TOP (R251.2), MODULE_MD (MODULE1.AC42), USB_PD_CONTROLLER (R237.1 R332.2), AUDIO_CODEC (R277.1), HDMI_CONVERTER (R228.2), T8CH_ (U33_5.3)
MD_GPIO_46: TOP (R250.2), MODULE_MD (MODULE1.AB41), USB_PD_CONTROLLER (R235.1 R331.2), AUDIO_CODEC (R278.1), HDMI_CONVERTER (R227.2), T8CH_ (U33_5.1)
MD_GPIO_47: MODULE_MD (MODULE1.AB39), MICROCONTROLLER (R362.2)
MD_GPIO_48: MODULE_MD (MODULE1.AC41), USB_PD_CONTROLLER (R178.1)
MD_GPIO_49: MODULE_MD (MODULE1.Y38), POWER (R496.2)
MD_GPIO_51: MODULE_MD (MODULE1.AA38), PCIE_NVME (R179.2), U_PCIE/U_PCIE_NVME/U_LOAD_SWITCH_5V (U27_6.1)
MD_GPIO_52: TOP (R174.1), MODULE_MD (MODULE1.AA42), HEADERS_JOMEGA (D25.2 D25.9 JOMEGA.72)
MD_GPIO_54: MODULE_MD (MODULE1.E35), WIFI_BLE (R312.1)
MD_GPIO_55: MODULE_MD (MODULE1.E36), PCIE (R322.1 R468.2), WIFI_BLE (R313.1)
MD_GPIO_56: MODULE_MD (MODULE1.W39), WIFI_BLE (R439.1)
MD_GPIO_63: MODULE_MD (MODULE1.AH42), MICROCONTROLLER (R409.2)
MD_GPIO_64: MODULE_MD (MODULE1.AF39), U_MIPI/U_TRANSLATOR_4CH (U21_2.2)
MD_GPIO_65: MODULE_MD (MODULE1.AH41), WIFI_BLE (R381.1)
MD_GPIO_67: MODULE_MD (MODULE1.W38), HEADERS_JMEDIA_JMISC (D86.2 JMEDIA.16)
MD_GPIO_68: MODULE_MD (MODULE1.W43), HEADERS_JMEDIA_JMISC (D87.2 JMEDIA.18)
MD_GPIO_69: MODULE_MD (MODULE1.V42), MICROCONTROLLER (R365.2)
MD_GPIO_70: MODULE_MD (MODULE1.AG40), MICROCONTROLLER (R363.2)
MD_GPIO_71: MODULE_MD (MODULE1.AG39), MICROCONTROLLER (R364.2)
MD_GPIO_73: MODULE_MD (MODULE1.AH40), HEADERS_JMEDIA_JMISC (D102.4 D102.7 JMISC.49)
MD_GPIO_74: MODULE_MD (MODULE1.AJ42), HEADERS_JMEDIA_JMISC (D102.5 D102.6 JMISC.51)
MD_GPIO_75: MODULE_MD (MODULE1.AH39), U_MIPI/U_TRANSLATOR_4CH (U21_2.3)
MD_GPIO_77: MODULE_MD (MODULE1.D34), U_HEADERS_JHAT/T8CH_ (U33_4.4)
MD_GPIO_78: MODULE_MD (MODULE1.AY12), MICROCONTROLLER (R361.2 R412.2)
MD_GPIO_79: TOP (R258.1), MODULE_MD (MODULE1.AW12), PUSHBUTTONS (C205.2 R401.1), HEADERS_JOMEGA (D25.5 D25.6 JOMEGA.76)
MD_GPIO_80: MODULE_MD (MODULE1.M45), U_HEADERS_JHAT/T8CH_ (U33_4.5)
MD_GPIO_81: MODULE_MD (MODULE1.M46), U_HEADERS_JHAT/T8CH_ (U33_4.3)
MD_GPIO_82: MODULE_MD (MODULE1.L45), U_MIPI/U_TRANSLATOR_4CH (U21_2.4)
MD_GPIO_83: MODULE_MD (MODULE1.L46), U_HEADERS_JHAT/T8CH_ (U33_2.6)
MD_GPIO_85: MODULE_MD (MODULE1.AA40), U_HEADERS_JHAT/T8CH_ (U33_2.4), WIFI_BLE (R379.1)
MD_GPIO_86: MODULE_MD (MODULE1.AA39), U_HEADERS_JHAT/T8CH_ (U33_2.7), WIFI_BLE (R378.1)
MD_GPIO_87: MODULE_MD (MODULE1.AB42), U_HEADERS_JHAT/T8CH_ (U33_2.5), WIFI_BLE (R377.1)
MD_GPIO_88: MODULE_MD (MODULE1.AB40), U_HEADERS_JHAT/T8CH_ (U33_4.9)
MD_GPIO_89: MODULE_MD (MODULE1.AD39), U_HEADERS_JHAT/T8CH_ (U33_4.6)
MD_GPIO_90: MODULE_MD (MODULE1.AE39), U_HEADERS_JHAT/T8CH_ (U33_3.9)
MD_GPIO_92: MODULE_MD (MODULE1.AE41), MICROCONTROLLER (R366.2)
MD_GPIO_93: MODULE_MD (MODULE1.V43), HDMI_CONVERTER (U22.D5)
MD_GPIO_94: MODULE_MD (MODULE1.C28), USB_PD_CONTROLLER (R161.1)
MD_GPIO_95: MODULE_MD (MODULE1.C35), MICROCONTROLLER (R410.2)
MD_GPIO_96: MODULE_MD (MODULE1.C34), MICROCONTROLLER (R411.2)
MD_GPIO_99: MODULE_MD (MODULE1.E25), MODULE_STRAPS_MD (R115.2 R116.2)
MD_GPIO_100: MODULE_MD (MODULE1.E24), WIFI_BLE (R388.1)
MD_GPIO_101: MODULE_MD (MODULE1.D24), WIFI_BLE (R438.1)
MD_GPIO_103: TOP (R433.2 R479.2), MODULE_MD (MODULE1.D23)
MD_GPIO_104: MODULE_MD (MODULE1.D25), USB_PD_CONTROLLER (R187.1)
MD_GPIO_105: MODULE_MD (MODULE1.E28), U_HEADERS_JHAT/T8CH_ (U33_3.8)
MD_GPIO_106: MODULE_MD (MODULE1.D27), U_HEADERS_JHAT/T8CH_ (U33_3.6)
MD_GPIO_107: MODULE_MD (MODULE1.E32), U_HEADERS_JHAT/T8CH_ (U33_3.3)
MD_GPIO_108: MODULE_MD (MODULE1.F27), U_HEADERS_JHAT/U_TRANSLATOR_4CH (U21_1.4)
MD_GPIO_109: MODULE_MD (MODULE1.E27), U_HEADERS_JHAT/T8CH_ (U33_2.1)
MD_LPASS_GPIO_110: MODULE_MD (MODULE1.F28), AUDIO_CODEC (R282.1)
MD_LPASS_GPIO_111: MODULE_MD (MODULE1.D30), AUDIO_CODEC (R281.1)
MD_LPASS_GPIO_112: MODULE_MD (MODULE1.E30), AUDIO_CODEC (R280.1)
MD_LPASS_GPIO_113: MODULE_MD (MODULE1.E31), AUDIO_CODEC (R279.1)
MD_LPASS_GPIO_115: MODULE_MD (MODULE1.D29), AUDIO_CODEC (R283.1)
MD_LPASS_GPIO_120: MODULE_MD (MODULE1.D31), HEADERS_JMEDIA_JMISC (D105.1 D105.10 JMISC.46)
MD_LPASS_GPIO_121: MODULE_MD (MODULE1.C32), HEADERS_JMEDIA_JMISC (D105.2 D105.9 JMISC.48)
MD_LPASS_GPIO_122: MODULE_MD (MODULE1.C31), HEADERS_JMEDIA_JMISC (D105.4 D105.7 JMISC.50)
MD_LPASS_GPIO_123: MODULE_MD (MODULE1.B33), HEADERS_JMEDIA_JMISC (D105.5 D105.6 JMISC.52)
MD_LPASS_GPIO_125: MODULE_MD (MODULE1.C29), HDMI_CONVERTER (U22.C2)
MD_LPASS_GPIO_126: MODULE_MD (MODULE1.B32), HDMI_CONVERTER (U22.D3)
MD_LPASS_GPIO_127: MODULE_MD (MODULE1.C30), HDMI_CONVERTER (U22.C1)
MD_LPASS_GPIO_129: MODULE_MD (MODULE1.A36), WIFI_BLE (R353.1)
MD_LPASS_GPIO_130: MODULE_MD (MODULE1.B35), WIFI_BLE (R343.1)
MD_LPASS_GPIO_131: MODULE_MD (MODULE1.B36), WIFI_BLE (R344.1 R347.1)
MD_LPASS_GPIO_132: MODULE_MD (MODULE1.A35), WIFI_BLE (R345.1 R348.1)
MD_PCIE0_2LANES.REFCLK_N: MODULE_MD (MODULE1.BC21), PCIE_PACKET_SWITCH (U34.AF34)
MD_PCIE0_2LANES.REFCLK_P: MODULE_MD (MODULE1.BC22), PCIE_PACKET_SWITCH (U34.AG35)
MD_PCIE0_2LANES.RX0_N: MODULE_MD (MODULE1.BE22), PCIE_PACKET_SWITCH (C327.2)
MD_PCIE0_2LANES.RX0_P: MODULE_MD (MODULE1.BE23), PCIE_PACKET_SWITCH (C326.2)
MD_PCIE0_2LANES.RX1_N: MODULE_MD (MODULE1.BF23), PCIE_PACKET_SWITCH (U34.A13)
MD_PCIE0_2LANES.RX1_P: MODULE_MD (MODULE1.BF24), PCIE_PACKET_SWITCH (U34.A11)
MD_PCIE0_2LANES.TX0_N: MODULE_MD (MODULE1.BE19), PCIE_PACKET_SWITCH (U34.B6)
MD_PCIE0_2LANES.TX0_P: MODULE_MD (MODULE1.BE20), PCIE_PACKET_SWITCH (U34.B4)
MD_PCIE0_2LANES.TX1_N: MODULE_MD (MODULE1.BF20), PCIE_PACKET_SWITCH (U34.A9)
MD_PCIE0_2LANES.TX1_P: MODULE_MD (MODULE1.BF21), PCIE_PACKET_SWITCH (U34.B10)
MD_PCIE1_4LANES.REFCLK_N: MODULE_MD (MODULE1.BC17), PCIE_NVME (D32.1 D32.10 J10.53)
MD_PCIE1_4LANES.REFCLK_P: MODULE_MD (MODULE1.BC18), PCIE_NVME (D32.2 D32.9 J10.55)
MD_PCIE1_4LANES.RX0_N: MODULE_MD (MODULE1.BF16), PCIE_NVME (D31.1 D31.10 J10.41)
MD_PCIE1_4LANES.RX0_P: MODULE_MD (MODULE1.BF17), PCIE_NVME (D31.2 D31.9 J10.43)
MD_PCIE1_4LANES.RX1_N: MODULE_MD (MODULE1.BE15), PCIE_NVME (D30.1 D30.10 J10.29)
MD_PCIE1_4LANES.RX1_P: MODULE_MD (MODULE1.BE16), PCIE_NVME (D30.2 D30.9 J10.31)
MD_PCIE1_4LANES.RX2_N: MODULE_MD (MODULE1.BD14), PCIE_NVME (D29.1 D29.10 J10.17)
MD_PCIE1_4LANES.RX2_P: MODULE_MD (MODULE1.BD15), PCIE_NVME (D29.2 D29.9 J10.19)
MD_PCIE1_4LANES.RX3_N: MODULE_MD (MODULE1.BC13), PCIE_NVME (D28.1 D28.10 J10.5)
MD_PCIE1_4LANES.RX3_P: MODULE_MD (MODULE1.BC14), PCIE_NVME (D28.2 D28.9 J10.7)
MD_PCIE1_4LANES.TX0_N: MODULE_MD (MODULE1.BF12), PCIE_NVME (D31.4 D31.7 J10.47)
MD_PCIE1_4LANES.TX0_P: MODULE_MD (MODULE1.BF13), PCIE_NVME (D31.5 D31.6 J10.49)
MD_PCIE1_4LANES.TX1_N: MODULE_MD (MODULE1.BE11), PCIE_NVME (D30.4 D30.7 J10.35)
MD_PCIE1_4LANES.TX1_P: MODULE_MD (MODULE1.BE12), PCIE_NVME (D30.5 D30.6 J10.37)
MD_PCIE1_4LANES.TX2_N: MODULE_MD (MODULE1.BD10), PCIE_NVME (D29.4 D29.7 J10.23)
MD_PCIE1_4LANES.TX2_P: MODULE_MD (MODULE1.BD11), PCIE_NVME (D29.5 D29.6 J10.25)
MD_PCIE1_4LANES.TX3_N: MODULE_MD (MODULE1.BC9), PCIE_NVME (D28.4 D28.7 J10.11)
MD_PCIE1_4LANES.TX3_P: MODULE_MD (MODULE1.BC10), PCIE_NVME (D28.5 D28.6 J10.13)
MD_QUP1_SE4_I2C_3V3.SCL: TOP (R155.2), POWER (U20.5), T8CH_ (U33_5.20), PCIE_PACKET_SWITCH (R311.2), PCIE_USB (R318.1)
MD_QUP1_SE4_I2C_3V3.SDA: TOP (R158.2), POWER (U20.6), T8CH_ (U33_5.18), PCIE_PACKET_SWITCH (R310.2), PCIE_USB (R189.1)
MD_SGMII0.RX_N: MODULE_MD (MODULE1.BF26), ETH_PHY (C112.2)
MD_SGMII0.RX_P: MODULE_MD (MODULE1.BE26), ETH_PHY (C247.2)
MD_SGMII0.TX_N: MODULE_MD (MODULE1.BC25), ETH_PHY (U1.42)
MD_SGMII0.TX_P: MODULE_MD (MODULE1.BC26), ETH_PHY (U1.40)
MD_USB0_3.1.HS_D_N: MODULE_MD (MODULE1.BD6), USB_USBC (D72.2 D72.9 J1.A7 J1.B7)
MD_USB0_3.1.HS_D_P: MODULE_MD (MODULE1.BD7), USB_USBC (D72.1 D72.10 J1.A6 J1.B6)
MD_USB0_3.1.SS_RX_N: MODULE_MD (MODULE1.BB1), USB_MUX (U6.17)
MD_USB0_3.1.SS_RX_P: MODULE_MD (MODULE1.BA1), USB_MUX (U6.16)
MD_USB0_3.1.SS_TX_N: MODULE_MD (MODULE1.BF6), USB_MUX (U6.12)
MD_USB0_3.1.SS_TX_P: MODULE_MD (MODULE1.BF5), USB_MUX (U6.11)
MD_USB1_2.0.HS_D_N: MODULE_MD (MODULE1.BF8), STM32 (R383.1)
MD_USB1_2.0.HS_D_P: MODULE_MD (MODULE1.BF9), STM32 (R382.1)
MIC_IN5_IN6.BIAS: AUDIO_CODEC (C110.2 U23.28), HEADERS_JOMEGA (D24.2 JOMEGA.61), HEADERS_JMEDIA_JMISC (D100.2 JMISC.33)
MIC_IN5_IN6.INN: AUDIO_CODEC (C254.2), HEADERS_JOMEGA (D21.2 JOMEGA.59)
MIC_IN5_IN6.INP: AUDIO_CODEC (C253.2), HEADERS_JOMEGA (D17.2 JOMEGA.57)
MUX_SSRX1_N: USB (C51.1), USB_MUX (U6.24)
MUX_SSRX1_P: USB (C50.1), USB_MUX (U6.25)
MUX_SSRX2_N: USB (C53.1), USB_MUX (U6.33)
MUX_SSRX2_P: USB (C52.1), USB_MUX (U6.34)
MUX_TX1_N: USB (R452.2), USB_MUX (U6.27)
MUX_TX1_P: USB (R451.2), USB_MUX (U6.28)
MUX_TX2_N: USB (R454.2), USB_MUX (U6.30)
MUX_TX2_P: USB (R453.2), USB_MUX (U6.31)
NetC12_2: ETH_PHY (5 pins), ETH_RJ45 (J2.1 J2.6 J2.7 J2.12)
NetC35_2: USB (C35.2 C37.2), USB_USBA (J7.10), U_USB/U_LOAD_SWITCH_5V (U27_1.7 U27_1.8 U27_1.9 U27_1.10)
NetC36_2: ETH_PHY (C36.2 R85.2), U_ETH/U_ETH_PHY/U_LOAD_SWITCH_5V (U27_3.1)
NetC76_1: POWER (R229.2 R273.2 TP60.X), POWER_DCDC_SOM (15 pins), POWER_REGULATORS_CARRIER (6 pins)
NetC107_2: HEADERS_UNO (JDIGITAL.16), STM32 (C107.2 C291.2 U3.K5), ANALOG_SWITCH (U28.3)
NetC119_2: POWER (R22.1 R150.1), POWER_REGULATORS_CARRIER (9 pins)
NetC147_2: USB (C147.2 C171.2), USB_USBA (J7.1), U_USB/U_LOAD_SWITCH_5V (U27_2.7 U27_2.8 U27_2.9 U27_2.10)
NetC209_2: AUDIO_CODEC (C209.2), HEADERS_JMEDIA_JMISC (D98.2 JMISC.29)
NetC217_2: AUDIO_CODEC (C217.2), HEADERS_JMEDIA_JMISC (D99.2 JMISC.31)
NetC224_2: PCIE_NVME (16 pins), U_PCIE/U_PCIE_NVME/U_LOAD_SWITCH_5V (U27_6.7 U27_6.8 U27_6.9 U27_6.10)
NetC248_2: AUDIO_CODEC (C248.2 U23.5), HEADERS_JMEDIA_JMISC (D104.1 D104.10 JMISC.36)
NetC295_2: AUDIO_CODEC (C295.2 U23.7), HEADERS_JMEDIA_JMISC (D104.2 D104.9 JMISC.38)
NetC342_1: POWER (D22.2 J8.5), CAN_PHY (C342.1 R506.2 U7.7)
NetC345_2: POWER (R496.1 R497.1), POWER_REGULATORS_CARRIER (C345.2 R130.1 U14.4)
NetC361_1: POWER (D23.2 J8.4), CAN_PHY (C361.1 R507.1 U7.6)
NetD16_1: HDMI_CONNECTOR (D16.1 D16.10 J4.13), HDMI_CONVERTER (U22.D6)
NetD16_2: HDMI_CONNECTOR (D16.2 D16.9 J4.15 R490.2), HDMI_CONVERTER (U22.D1)
NetD16_4: HDMI (R112.2), HDMI_CONNECTOR (D16.4 D16.7 J4.19), HDMI_CONVERTER (U22.C4)
NetD16_5: HDMI_CONNECTOR (D16.5 D16.6 J4.16 R491.2), HDMI_CONVERTER (U22.D2)
NetD61_2: TOP (R219.1), HEADERS_JCTL (D61.2 JCTL.3 TP58.X)
NetD62_2: TOP (R433.1), HEADERS_JCTL (D62.2 JCTL.5 TP59.X)
NetD103_1: AUDIO_CODEC (U23.13), HEADERS_JMEDIA_JMISC (D103.1 D103.10 JMISC.28)
NetD103_2: AUDIO_CODEC (U23.12), HEADERS_JMEDIA_JMISC (D103.2 D103.9 JMISC.30)
NetD103_4: AUDIO_CODEC (U23.10), HEADERS_JMEDIA_JMISC (D103.4 D103.7 JMISC.32)
NetD103_5: AUDIO_CODEC (R481.2), HEADERS_JMEDIA_JMISC (D103.5 D103.6 JMISC.34)
NetD104_4: AUDIO_CODEC (U23.6), HEADERS_JMEDIA_JMISC (D104.4 D104.7 JMISC.40)
NetD104_5: AUDIO_CODEC (U23.8), HEADERS_JMEDIA_JMISC (D104.5 D104.6 JMISC.42)
NetJ2_13: ETH (R111.1), ETH_RJ45 (J2.13)
NetJ2_17: ETH (R110.1), ETH_RJ45 (J2.17)
NetJOMEGA_54: HEADERS_JOMEGA (JOMEGA.54), PCIE_USB (U24.B33)
NetJOMEGA_56: HEADERS_JOMEGA (JOMEGA.56), PCIE_USB (U24.A36)
NetJOMEGA_58: HEADERS_JOMEGA (JOMEGA.58), PCIE_USB (U24.A46)
NetJOMEGA_60: HEADERS_JOMEGA (JOMEGA.60), PCIE_USB (U24.B43)
NetMODULE1_A6: TOP (R216.1 U25.4), MODULE_CONTROL (MODULE1.A6)
NetMODULE1_BA29: MODULE_SAIL (MODULE1.BA29), MODULE_SAIL_FLASH (R59.1 TP27.X U2.C2)
NetMODULE1_BB28: MODULE_SAIL (MODULE1.BB28), MODULE_SAIL_FLASH (TP54.X U2.D5)
NetMODULE1_BB29: MODULE_SAIL (MODULE1.BB29), MODULE_SAIL_FLASH (R58.1 TP52.X U2.C4)
NetMODULE1_BB43: TOP (R488.1), MODULE_SAIL (MODULE1.BB43)
NetMODULE1_BC28: MODULE_SAIL (MODULE1.BC28), MODULE_SAIL_FLASH (TP31.X U2.C3)
NetMODULE1_BC29: MODULE_SAIL (MODULE1.BC29), MODULE_SAIL_FLASH (TP28.X U2.B2)
NetMODULE1_BD28: MODULE_SAIL (MODULE1.BD28), MODULE_SAIL_FLASH (TP55.X U2.E3)
NetMODULE1_BD29: MODULE_SAIL (MODULE1.BD29), MODULE_SAIL_FLASH (R57.1 TP53.X U2.D4)
NetMODULE1_BD41: MODULE_SAIL (MODULE1.BD41), MODULE_SAIL_FLASH (R60.1 TP26.X U2.A4)
NetMODULE1_BE28: MODULE_SAIL (MODULE1.BE28), MODULE_SAIL_FLASH (TP56.X U2.E2)
NetMODULE1_BE29: MODULE_SAIL (MODULE1.BE29), MODULE_SAIL_FLASH (TP50.X U2.D3)
NetMODULE1_BE36: MODULE (TP93.X), MODULE_SAIL (MODULE1.BE36)
NetMODULE1_BF28: MODULE_SAIL (MODULE1.BF28), MODULE_SAIL_FLASH (TP51.X U2.D2)
NetMODULE1_BF29: MODULE_SAIL (MODULE1.BF29), MODULE_SAIL_FLASH (TP57.X U2.E1)
NetMODULE1_BF36: MODULE (TP32.X), MODULE_SAIL (MODULE1.BF36)
NetMODULE1_D28: TOP (R125.2), MODULE_CONTROL (MODULE1.D28)
NetPB1_3: TOP (R188.1 R477.1), PUSHBUTTONS (PB1.3 PB1.4)
NetQ3_2: USB_PD_CONTROLLER (R368.1), POWER (Q3.2 R249.1 TP82.X)
NetQ3_3: USB_PD_CONTROLLER (R367.1), POWER (Q3.3)
NetQ4_3: TOP (R174.2), HEADERS_JCTL (Q4.3 R166.2)
NetQ4_6: TOP (R346.2), HEADERS_JCTL (Q4.6 R458.2)
NetR23_1: WIFI_BLE (R23.1 U12.30), U_PCIE/U_WIFI_BLE/U_TRANSLATOR_4CH (U21_4.3)
NetR24_2: WIFI_BLE (R24.2), U_PCIE/U_WIFI_BLE/U_TRANSLATOR_4CH (U21_4.8)
NetR25_2: USB (R25.2), U_USB/U_LOAD_SWITCH_5V (U27_1.4)
NetR26_2: USB (R26.2), U_USB/U_LOAD_SWITCH_5V (U27_2.4)
NetR62_1: ETH (TP45.X), ETH_PHY (R62.1 R77.2 U1.26)
NetR63_1: ETH (TP44.X), ETH_PHY (R63.1 R78.2 U1.27)
NetR64_1: ETH (TP46.X), ETH_PHY (R64.1 R79.2 U1.45)
NetR65_1: ETH (TP47.X), ETH_PHY (R65.1 R80.2 U1.29)
NetR66_1: ETH (U9.2), ETH_PHY (R66.1 R81.2 U1.49)
NetR67_1: ETH (U8.2), ETH_PHY (R67.1 R82.2 U1.48)
NetR68_1: ETH (TP48.X), ETH_PHY (R68.1 R83.2 U1.46)
NetR97_1: USB_MUX (R97.1 R406.2), USB_PD_CONTROLLER (R102.1)
NetR98_1: USB_MUX (R98.1 R407.2), USB_PD_CONTROLLER (R103.1)
NetR112_1: HDMI (R112.1 R269.2), U_MIPI/U_MIPI_MUX (U10_1.17)
NetR140_2: MICROCONTROLLER (R140.2), U_MICROCONTROLLER/U_TRANSLATOR_4CH (U21_3.10)
NetR150_2: POWER (R150.2), POWER_REGULATORS_CARRIER (U16.1)
NetR151_2: MICROCONTROLLER (R151.2), U_MICROCONTROLLER/U_TRANSLATOR_4CH (U21_3.9)
NetR152_2: MICROCONTROLLER (R152.2), U_MICROCONTROLLER/U_TRANSLATOR_4CH (U21_3.8)
NetR153_2: MICROCONTROLLER (R153.2), U_MICROCONTROLLER/U_TRANSLATOR_4CH (U21_3.7)
NetR154_2: USB (R154.2), U_USB/U_LOAD_SWITCH_5V (U27_2.1), PCIE_USB (U24.A48)
NetR161_2: USB_PD_CONTROLLER (R161.2), U_USB/U_USB_PD_CONTROLLER/T8CH_ (U33_1.5)
NetR162_2: VIDEO (R162.2), U_MIPI/U_MIPI_MUX (U10_2.2)
NetR172_2: USB_PD_CONTROLLER (R172.2), U_USB/U_USB_PD_CONTROLLER/T8CH_ (U33_1.8)
NetR173_1: USB_PD_CONTROLLER (R173.1), U_USB/U_USB_PD_CONTROLLER/T8CH_ (U33_1.13)
NetR178_2: USB_PD_CONTROLLER (R178.2), U_USB/U_USB_PD_CONTROLLER/T8CH_ (U33_1.6)
NetR182_2: USB (R182.2), U_USB/U_LOAD_SWITCH_5V (U27_1.1), PCIE_USB (U24.B34)
NetR183_2: PCIE_NVME (R183.2), U_PCIE/U_PCIE_NVME/U_LOAD_SWITCH_5V (U27_6.4)
NetR186_2: USB_PD_CONTROLLER (R186.2), U_USB/U_USB_PD_CONTROLLER/T8CH_ (U33_1.1)
NetR187_2: USB_PD_CONTROLLER (R187.2), U_USB/U_USB_PD_CONTROLLER/T8CH_ (U33_1.7)
NetR215_1: USB_PD_CONTROLLER (U5.43), POWER (R215.1 U29.3)
NetR235_2: USB_PD_CONTROLLER (R235.2), U_USB/U_USB_PD_CONTROLLER/T8CH_ (U33_1.3)
NetR237_2: USB_PD_CONTROLLER (R237.2), U_USB/U_USB_PD_CONTROLLER/T8CH_ (U33_1.4)
NetR268_1: VIDEO (R268.1), U_MIPI/U_MIPI_MUX (U10_2.16)
NetR315_2: PCIE (R315.2), U_PCIE/U_TRANSLATOR_4CH (U21_5.5)
NetR323_2: PCIE (R323.2), U_PCIE/U_TRANSLATOR_4CH (U21_5.7)
NetR324_2: USB_PD_CONTROLLER (R324.2), U_USB/U_USB_PD_CONTROLLER/T8CH_ (U33_1.9)
NetR325_1: USB_PD_CONTROLLER (R325.1), U_USB/U_USB_PD_CONTROLLER/T8CH_ (U33_1.12)
NetR336_2: POWER (R336.2), U_POWER/U_LOAD_SWITCH_5V (U27_4.1)
NetR337_2: POWER (R337.2), U_POWER/U_LOAD_SWITCH_5V (U27_5.1)
NetR339_2: POWER (R339.2), U_POWER/U_LOAD_SWITCH_5V (U27_4.4)
NetR341_2: POWER (R341.2), U_POWER/U_LOAD_SWITCH_5V (U27_5.4)
NetR342_2: ETH_PHY (R342.2), U_ETH/U_ETH_PHY/U_LOAD_SWITCH_5V (U27_3.4)
NetR349_2: TOP (R349.2), MODULE_CONTROL (R402.2 U36.2)
NetR350_2: TOP (R350.2), MODULE_CONTROL (R489.2 U4.6 U19.2)
NetR361_1: MICROCONTROLLER (R361.1), U_MICROCONTROLLER/U_TRANSLATOR_4CH (U21_3.2)
NetR362_1: MICROCONTROLLER (R362.1), U_MICROCONTROLLER/U_TRANSLATOR_4CH (U21_3.3)
NetR363_1: MICROCONTROLLER (R363.1), U_MICROCONTROLLER/U_TRANSLATOR_4CH (U21_3.4)
NetR364_1: MICROCONTROLLER (R364.1), U_MICROCONTROLLER/U_TRANSLATOR_4CH (U21_3.5)
NetR386_2: VIDEO (R386.2), U_MIPI/U_MIPI_MUX (U10_3.2)
NetR392_1: VIDEO (R392.1), U_MIPI/U_MIPI_MUX (U10_3.16)
NetR393_1: VIDEO (R393.1), U_MIPI/U_MIPI_MUX (U10_1.2)
NetR394_1: VIDEO (R394.1), U_MIPI/U_MIPI_MUX (U10_1.16)
NetR395_1: VIDEO (R395.1), U_MIPI/U_TRANSLATOR_4CH (U21_2.7)
NetR396_2: VIDEO (R396.2), U_MIPI/U_TRANSLATOR_4CH (U21_2.5)
NetR428_2: WIFI_BLE (R428.2), U_PCIE/U_WIFI_BLE/U_TRANSLATOR_4CH (U21_4.7)
NetR429_2: WIFI_BLE (R429.2), U_PCIE/U_WIFI_BLE/U_TRANSLATOR_4CH (U21_4.5)
NetR461_2: WIFI_BLE (R461.2), U_PCIE/U_WIFI_BLE/U_TRANSLATOR_4CH (U21_4.4)
NetR463_2: PCIE_PACKET_SWITCH (U34.AN35), WIFI_BLE (R463.2), U_PCIE/U_WIFI_BLE/U_TRANSLATOR_4CH (U21_4.9)
NetR464_2: PCIE_PACKET_SWITCH (U34.G1), WIFI_BLE (R464.2 R467.2), U_PCIE/U_WIFI_BLE/U_TRANSLATOR_4CH (U21_4.10)
NetR465_1: WIFI_BLE (R465.1 R466.2 U12.31), U_PCIE/U_WIFI_BLE/U_TRANSLATOR_4CH (U21_4.2)
NetTP2_X: USB (TP2.X), USB_MUX (U6.22)
NetTP3_X: USB (TP3.X), USB_MUX (U6.19)
NetTP4_X: USB (TP4.X), USB_MUX (U6.21)
NetTP5_X: USB (TP5.X), USB_MUX (U6.20)
NetTP40_X: TOP (TP40.X), ETH_PHY (U1.44)
NetTP41_X: TOP (TP41.X), ETH_PHY (U1.30)
NetTP42_X: TOP (TP42.X), ETH_PHY (U1.24)
NetTP43_X: ETH (TP43.X), ETH_PHY (U1.25)
NetTP49_X: ETH (TP49.X), ETH_PHY (U1.31)
NetU24_A40: PCIE_PACKET_SWITCH (U34.K2), PCIE_USB (U24.A40)
NetU24_B36: PCIE_PACKET_SWITCH (U34.AK34), PCIE_USB (U24.B36)
NRST: HEADERS_UNO (JANALOG.3 JSPI.5), MICROCONTROLLER (R140.1), STM32 (C270.2 R181.1 R384.1 TP35.X)
~{PM_RESIN_N_3V3}: TOP (R216.2 R487.1 U25.2), HEADERS_JOMEGA (D26.1 D26.10 JOMEGA.78), HEADERS_JCTL (D67.2 JCTL.8)
~{POWER_DISABLE_7-24V}: TOP (Q7.3), POWER_DCDC_SOM (5 pins), HEADERS_JOMEGA (JOMEGA.87), HEADERS_JCTL (R486.1)
~{PWR_EN_N_3V3}: TOP (R188.2 R219.2 R350.1), HEADERS_JOMEGA (D25.4 D25.7 JOMEGA.74)
PA0: STM32 (U3.L2), HEADERS_JMEDIA_JMISC (JMISC.20)
PA1: STM32 (U3.L4), HEADERS_JMEDIA_JMISC (JMISC.22)
PA2: STM32 (U3.M3), HEADERS_JMEDIA_JMISC (JMISC.24)
PA4: HEADERS_UNO (JANALOG.9), STM32 (U3.N3)
PA5: HEADERS_UNO (JANALOG.10), STM32 (U3.P2)
PA6: STM32 (U3.R2), HEADERS_JMEDIA_JMISC (JMISC.17)
PA7: STM32 (U3.P3), HEATSINK_FAN (R261.1 R262.2)
PA8: STM32 (R376.1 U3.G11), QWIIC (D80.2 J13.4 TP72.X)
PA9: STM32 (U3.G13), HEADERS_JMEDIA_JMISC (JMISC.1)
PA10: HEADERS_JOMEGA (JOMEGA.92), STM32 (U3.F13)
PA11: STM32 (U3.F15), HEADERS_JMEDIA_JMISC (JMISC.23)
PA12: STM32 (U3.F14), HEADERS_JMEDIA_JMISC (JMISC.25)
PA13: MICROCONTROLLER (R152.1), STM32 (TP67.X U3.F12)
PA14: MICROCONTROLLER (R153.1), STM32 (TP68.X U3.C15)
PA_VBUS: USB_USBC (7 pins), USB_PD_CONTROLLER (D4.A U5.41 U5.42), POWER (C294.2 Q5.D R213.2 U29.1)
PB0: HEADERS_UNO (JDIGITAL.3), STM32 (U3.R3)
PB1: HEADERS_UNO (JDIGITAL.4), STM32 (U3.L6)
PB2: HEADERS_UNO (JDIGITAL.7), STM32 (U3.P4)
PB3: HEADERS_UNO (JDIGITAL.8), STM32 (TP70.X U3.B7)
PB4: HEADERS_UNO (JDIGITAL.9), STM32 (U3.C7)
PB5: HEADERS_UNO (JDIGITAL.6), STM32 (U3.E7)
PB6: HEADERS_UNO (JDIGITAL.5), STM32 (U3.E8)
PB7: HEADERS_UNO (JDIGITAL.10), STM32 (U3.A6)
PB10: HEADERS_UNO (JDIGITAL.2), STM32 (U3.M10)
PB11: HEADERS_UNO (JDIGITAL.1), STM32 (U3.P11)
PB12: HEADERS_UNO (JDIGITAL.11), STM32 (U3.P14)
PB13: HEADERS_UNO (JDIGITAL.14), STM32 (U3.N13)
PB14: HEADERS_UNO (JDIGITAL.13), STM32 (U3.K11)
PB15: HEADERS_UNO (JDIGITAL.12), STM32 (U3.M13)
PC0: HEADERS_JOMEGA (JOMEGA.39), STM32 (U3.L1)
PC1: HEADERS_JOMEGA (JOMEGA.41), STM32 (U3.K2)
PC2: HEADERS_JOMEGA (JOMEGA.43), STM32 (U3.M1)
PC3: HEADERS_JOMEGA (JOMEGA.45), STM32 (U3.M2)
PC6: STM32 (U3.J15), U_MICROCONTROLLER/U_LED/U_LED_RGB (R207_4.1)
PC7: STM32 (U3.H14), HEADERS_JMEDIA_JMISC (JMISC.3)
PC8: STM32 (U3.H13), HEADERS_JMEDIA_JMISC (JMISC.5)
PC9: STM32 (R375.1 U3.G14), QWIIC (D81.2 J13.3 TP73.X)
PC10: HEADERS_UNO (JSPI.3), STM32 (U3.D12)
PC11: STM32 (U3.B14), HEADERS_JMEDIA_JMISC (JMISC.9)
PC12: HEADERS_UNO (JSPI.4), STM32 (U3.B15)
PCIE1_REFCLK0_N: PCIE_PACKET_SWITCH (U34.W35), WIFI_BLE (U12.33)
PCIE1_REFCLK0_P: PCIE_PACKET_SWITCH (U34.U35), WIFI_BLE (U12.34)
PCIE1_RX0_N: PCIE_PACKET_SWITCH (U34.B30), WIFI_BLE (U12.36)
PCIE1_RX0_P: PCIE_PACKET_SWITCH (U34.B32), WIFI_BLE (U12.37)
PCIE1_TX0_CAP_N: PCIE_PACKET_SWITCH (C307.1), WIFI_BLE (U12.39)
PCIE1_TX0_CAP_P: PCIE_PACKET_SWITCH (C299.1), WIFI_BLE (U12.40)
PCIE2_REFCLK0_N: PCIE_PACKET_SWITCH (U34.AC35), PCIE_USB (U24.B41)
PCIE2_REFCLK0_P: PCIE_PACKET_SWITCH (U34.AA35), PCIE_USB (U24.A45)
PCIE2_RX0_N: PCIE_PACKET_SWITCH (U34.A27), PCIE_USB (C325.1)
PCIE2_RX0_P: PCIE_PACKET_SWITCH (U34.B26), PCIE_USB (C324.1)
PCIE2_TX0_CAP_N: PCIE_PACKET_SWITCH (C323.1), PCIE_USB (U24.A42)
PCIE2_TX0_CAP_P: PCIE_PACKET_SWITCH (C322.1), PCIE_USB (U24.B39)
PD0: STM32 (U3.E10), CAN_PHY (U7.4)
PD1: STM32 (U3.C12), CAN_PHY (U7.1)
PD3: STM32 (U3.A14), HEADERS_JMEDIA_JMISC (JMISC.11)
PD5: HEADERS_JOMEGA (JOMEGA.86), STM32 (U3.B12)
PD9: HEADERS_JOMEGA (JOMEGA.94), STM32 (U3.P15)
PD10: STM32 (U3.N14), U_MICROCONTROLLER/U_LED/U_LED_RGB (R208_2.2)
PD11: STM32 (U3.N15), U_MICROCONTROLLER/U_LED/U_LED_RGB (R205_3.2)
PD12: HEADERS_JOMEGA (JOMEGA.47), STM32 (U3.M14)
PD13: HEADERS_JOMEGA (JOMEGA.49), STM32 (U3.L13)
PD14: HEADERS_JOMEGA (JOMEGA.51), STM32 (U3.J11)
PD15: HEADERS_JOMEGA (JOMEGA.53), STM32 (U3.K12)
PE1: STM32 (U3.B5), HEADERS_JMEDIA_JMISC (JMISC.7)
PE2: STM32 (U3.B3), HEADERS_JMEDIA_JMISC (JMISC.2)
PE3: STM32 (U3.D5), HEADERS_JMEDIA_JMISC (JMISC.4)
PE4: STM32 (U3.C4), HEADERS_JMEDIA_JMISC (JMISC.6)
PE5: STM32 (U3.D4), HEADERS_JMEDIA_JMISC (JMISC.8)
PE6: STM32 (U3.F6), HEADERS_JMEDIA_JMISC (JMISC.10)
PE7: STM32 (U3.L8), HEADERS_JMEDIA_JMISC (JMISC.12)
PE8: STM32 (U3.M8), HEADERS_JMEDIA_JMISC (JMISC.14)
PE12: HEADERS_UNO (JANALOG.11), STM32 (U3.L9)
PE13: HEADERS_UNO (JANALOG.12), STM32 (U3.P10)
PE14: HEADERS_UNO (JANALOG.13), STM32 (U3.N10)
PE15: HEADERS_UNO (JANALOG.14), STM32 (U3.R11)
PF0: STM32 (R373.1 U3.E1), HEADERS_JMEDIA_JMISC (JMISC.18)
PF1: STM32 (R374.1 U3.G4), HEADERS_JMEDIA_JMISC (JMISC.16)
PF4: STM32 (U3.G1), HEADERS_JMEDIA_JMISC (JMISC.13)
PF6: HEADERS_JOMEGA (JOMEGA.98), STM32 (U3.H3)
PF7: HEADERS_JOMEGA (JOMEGA.100), STM32 (U3.H2)
PF14: HEADERS_UNO (JSPI.1), STM32 (U3.M7)
PG2: STM32 (U3.L15), U_MICROCONTROLLER/U_LED/U_LED_RGB (R205_4.2)
PG3: STM32 (U3.J12), U_MICROCONTROLLER/U_LED/U_LED_RGB (R205_1.2)
PG4: STM32 (U3.K14), U_MICROCONTROLLER/U_LED/U_LED_RGB (R205_2.2)
PG5: STM32 (U3.K15), U_MICROCONTROLLER/U_LED/U_LED_RGB (R208_3.2)
PG6: STM32 (U3.J13), U_MICROCONTROLLER/U_LED/U_LED_RGB (R208_1.2)
PG8: STM32 (U3.J14), U_MICROCONTROLLER/U_LED/U_LED_RGB (R208_4.2)
PG9: MICROCONTROLLER (R365.1), STM32 (U3.B9)
PG10: MICROCONTROLLER (R366.1), STM32 (U3.A9)
PG11: MICROCONTROLLER (R408.1), STM32 (U3.D8)
PG12: MICROCONTROLLER (R409.1), STM32 (U3.C8)
PG13: MICROCONTROLLER (R410.1), STM32 (U3.B8)
PG14: MICROCONTROLLER (R411.1), STM32 (U3.A8)
PG15: STM32 (U3.A7), HEATSINK_FAN (R264.2)
PH2: STM32 (U3.N1), LED_MATRIX (R108.2)
PH3: STM32 (U3.N2), LED_MATRIX (R195.2)
PH4: STM32 (U3.P1), LED_MATRIX (R196.2)
PH5: STM32 (U3.K6), LED_MATRIX (R197.2)
PH6: STM32 (U3.N11), LED_MATRIX (R198.2)
PH7: STM32 (U3.M11), LED_MATRIX (R199.2)
PH8: STM32 (U3.N12), HEADERS_JMEDIA_JMISC (JMISC.21)
PH9: STM32 (U3.P13), LED_MATRIX (R200.2)
PH10: STM32 (U3.K10), LED_MATRIX (R201.2)
PH11: HEADERS_UNO (JDIGITAL.18), STM32 (R372.1 U3.M12)
PH12: HEADERS_UNO (JDIGITAL.17), STM32 (R371.1 U3.R14)
PH13: STM32 (U3.E15), LED_MATRIX (R202.2)
PH14: STM32 (U3.E14), LED_MATRIX (R203.2)
PH15: STM32 (U3.E13), LED_MATRIX (R204.2)
PI2: HEADERS_JOMEGA (JOMEGA.55), STM32 (U3.F10)
PI5: STM32 (U3.A4), HEADERS_JMEDIA_JMISC (JMISC.19)
PI7: STM32 (U3.B4), HEADERS_JMEDIA_JMISC (JMISC.15)
PI8: MICROCONTROLLER (R184.2), STM32 (U3.E4), ANALOG_SWITCH (U28.6)
PI9: HEADERS_JOMEGA (JOMEGA.88), STM32 (U3.E2)
PI11: STM32 (U3.F3), CAN_PHY (U7.8)
PK0: STM32 (U3.M15), U_MICROCONTROLLER/U_LED/U_LED_RGB (R207_3.1)
PK1: STM32 (U3.L14), U_MICROCONTROLLER/U_LED/U_LED_RGB (R207_2.1)
PK2: STM32 (U3.K13), U_MICROCONTROLLER/U_LED/U_LED_RGB (R207_1.1)
PK10: TOP (R484.2), STM32 (U3.B2)
PK11: TOP (D44.A R510.1 R511.2), STM32 (U3.C2)
PK13: TOP (R482.2), STM32 (U3.B1)
PM_PS_HOLD: MODULE_CONTROL (MODULE1.C33), HEADERS_JOMEGA (D25.1 D25.10 JOMEGA.70)
RST_N_3V3: PCIE (R329.2), PCIE_PACKET_SWITCH (R143.2), U_PCIE/U_TRANSLATOR_4CH (U21_5.8)
RTSS_IO_4: MODULE_SAIL (MODULE1.BE39), MODULE_STRAPS_SAIL (R43.2 R56.2)
RTSS_IO_6: MODULE_SAIL (MODULE1.BF37), MODULE_STRAPS_SAIL (R40.2 R53.2)
RTSS_IO_7: MODULE_SAIL (MODULE1.BE37), MODULE_STRAPS_SAIL (R41.2 R54.2)
RTSS_IO_10: MODULE_SAIL (MODULE1.BC36), MODULE_STRAPS_SAIL (R32.2 R45.2)
RTSS_IO_11: MODULE_SAIL (MODULE1.BC37), MODULE_STRAPS_SAIL (R33.2 R46.2)
RTSS_IO_12: MODULE_SAIL (MODULE1.BD36), MODULE_STRAPS_SAIL (R34.2 R47.2)
RTSS_IO_14: MODULE_SAIL (MODULE1.BD39), MODULE_STRAPS_SAIL (R35.2 R48.2)
RTSS_IO_15: MODULE_SAIL (MODULE1.BC38), MODULE_STRAPS_SAIL (R36.2 R49.2)
RTSS_IO_16: MODULE_SAIL (MODULE1.BB38), MODULE_STRAPS_SAIL (R38.2 R51.2)
RTSS_IO_17: MODULE_SAIL (MODULE1.BC39), MODULE_STRAPS_SAIL (R39.2 R52.2)
RTSS_IO_18: MODULE_SAIL (MODULE1.AY35), MODULE_STRAPS_SAIL (R37.2 R50.2)
RTSS_IO_21: MODULE_SAIL (MODULE1.BA34), MODULE_STRAPS_SAIL (R42.2 R55.2)
RTSS_IO_51: MODULE_SAIL (MODULE1.AU46), MODULE_STRAPS_SAIL (R31.2 R44.2)
RTSS_IO_58_FORCE_USB_BOOT_SPX3_1P8: TOP (R346.1), MODULE_SAIL (MODULE1.BF40)
RTSS_PS_HOLD_SPX3_1P8: TOP (R488.2), HEADERS_JOMEGA (D26.4 D26.7 JOMEGA.82)
RTSS_RESIN_N: MODULE_SAIL (MODULE1.AY43), HEADERS_JOMEGA (D26.2 D26.9 JOMEGA.80)
SAIL_JTAG.SRST_N: MODULE_SAIL (MODULE1.AW37 TP65.X), HEADERS_JOMEGA (D39.1 D39.10 JOMEGA.71)
SAIL_JTAG.TCK: MODULE_SAIL (MODULE1.AW36 TP64.X), HEADERS_JOMEGA (D38.5 D38.6 JOMEGA.69)
SAIL_JTAG.TDI: MODULE_SAIL (MODULE1.BA37 TP63.X), HEADERS_JOMEGA (D38.4 D38.7 JOMEGA.67)
SAIL_JTAG.TDO: MODULE_SAIL (MODULE1.BA36 TP62.X), HEADERS_JOMEGA (D38.2 D38.9 JOMEGA.65)
SAIL_JTAG.TMS: MODULE_SAIL (MODULE1.AY36 TP61.X), HEADERS_JOMEGA (D38.1 D38.10 JOMEGA.63)
SAIL_JTAG.TRST_N: MODULE_SAIL (MODULE1.AY37 TP66.X), HEADERS_JOMEGA (D39.2 D39.9 JOMEGA.73)
SLEEP_CLK: MODULE_CONTROL (MODULE1.U41), WIFI_BLE (R440.1)
USB1_CAP_SSTX_N: HEADERS_JOMEGA (D18.2 D18.9 JOMEGA.20), PCIE_USB (C280.2)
